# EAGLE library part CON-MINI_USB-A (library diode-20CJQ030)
Various Mini-USB Type A Connectors
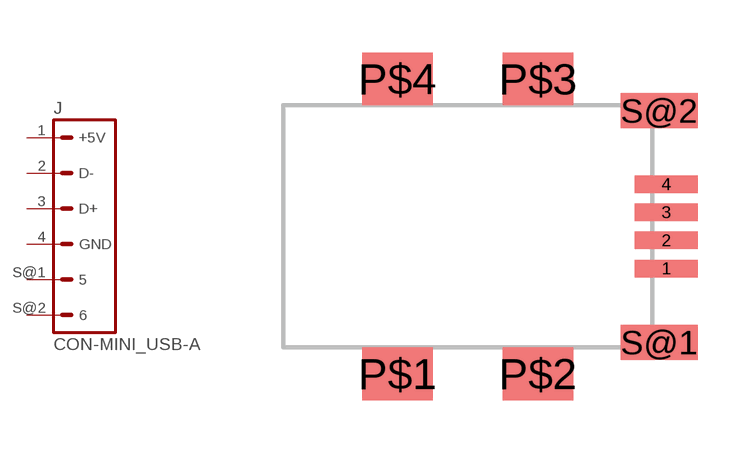
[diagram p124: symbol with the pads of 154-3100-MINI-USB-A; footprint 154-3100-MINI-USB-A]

Designator prefix J

## CON-MINI_USB-A-1  [154-3100-MINI-USB-A]
1  +5V  pas
2  D-  pas
3  D+  pas
4  GND  pas
S@1  5  pas
S@2  6  pas

## Footprint 154-3100-MINI-USB-A (pad centres in mm)
Kobiconn's 154-3100 Mini USB A Type Receptacle SPECIFICATIONS: Voltage rating: 30VAC(rms) Current rating: 1 Amp Contact resistance: 50m? Max. Insulation resistance: 100M? Min. Dielectric strength: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
smd 1.8 x 0.5: 1 10.9,2.25; 2 10.9,3.05; 3 10.9,3.85; 4 10.9,4.65
smd 2 x 1.5: P$1 3.25,-0.75; P$2 7.25,-0.75; P$3 7.25,7.65; P$4 3.25,7.65
smd 2.2 x 1: S@1 10.7,0.15; S@2 10.7,6.75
